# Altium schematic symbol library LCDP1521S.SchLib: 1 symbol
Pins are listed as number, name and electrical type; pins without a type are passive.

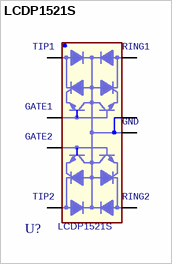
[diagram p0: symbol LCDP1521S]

## LCDP1521S
designator U?
footprint ST_SO8
pins: 1 TIP1, 2 GATE, 3 GATE2, 4 TIP2, 5 RING2, 6 GND, 7 GND1, 8 RING1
